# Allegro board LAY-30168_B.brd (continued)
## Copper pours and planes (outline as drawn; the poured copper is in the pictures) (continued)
N99816488 on TOP (solid shape): 101.6,9.68 101.6,6.99 101.6,6.97 101.58,6.95 100.99,5.58 101.58,4.21 101.6,4.19 101.6,4.17 101.6,3.08 101.35,2.83 99.31,2.83 99.06,3.08 99.06,9.68 99.31,9.94 101.35,9.94
N99816488 on BOTTOM (solid shape): 119.25,10.37 119.25,8.54 119,8.29 99.31,8.29 99.06,8.54 99.06,10.54 100.27,11.75 117.87,11.75
N99825452 on TOP (solid shape): 131.6,23.77 132.56,23.77 132.72,23.62 132.72,22.73 132.84,22.61 132.84,21.46 131.83,20.45 131.32,20.45 131.19,20.32 131.19,19.05 130.94,18.8 130.58,18.8 130.56,18.82 130.05,18.82 130.03,18.8 128.02,18.8 127.76,19.05 127.76,19.81 127.76,22.78 127.81,22.83 127.91,22.83 128.02,22.73 128.02,21.67 128.88,20.8 130.3,20.8 131.6,22.1 131.6,23.19 131.42,23.37 130.66,23.37 130.62,23.41 130.57,23.41 130.45,23.52 129.79,23.52 129.72,23.6 129.72,23.7 129.79,23.77 131.6,23.77
N99833003 on TOP (solid shape): 96.27,2.41 96.27,0.76 96.14,0.64 86.61,0.64 86.49,0.76 86.49,2.41 86.74,2.67 96.01,2.67
N99833003 on BOTTOM (solid shape): 96.27,2.41 96.27,0.76 96.14,0.64 86.61,0.64 86.49,0.76 86.49,2.41 86.74,2.67 96.01,2.67
N99833017 on TOP (solid shape): 91.31,7.87 91.31,6.73 91.31,6.7 91.29,6.69 91.16,6.5 91.18,6.27 91.18,6.24 91.16,6.21 91.14,6.18 90.22,6.18 90.14,6.11 90.14,5.26 90.17,5.24 90.17,5.23 90.22,5.14 90.3,5.07 90.32,5.05 90.32,5.03 90.32,3.48 90.3,3.45 90.2,3.45 90.13,3.49 90.1,3.56 90.07,3.78 89.98,3.99 89.97,4 89.97,4.22 89.79,4.4 88.19,4.4 87.88,4.71 87.88,7.34 87.91,7.36 88.82,7.36 89.2,6.98 90.96,6.98 91.03,7.06 91.03,7.87 91.06,7.9 91.29,7.9
N99834989 on TOP (solid shape): 85.6,2.41 85.6,0.76 85.47,0.64 75.95,0.64 75.82,0.76 75.82,2.41 76.07,2.67 85.34,2.67
N99834989 on BOTTOM (solid shape): 85.6,2.41 85.6,0.76 85.47,0.64 75.95,0.64 75.82,0.76 75.82,2.41 76.07,2.67 85.34,2.67
N99834993 on TOP (solid shape): 80.64,7.87 80.64,6.36 80.47,6.18 79.25,6.18 79.15,6.08 79.15,5.69 79.65,5.18 79.65,3.48 79.63,3.45 79.53,3.45 79.46,3.49 79.43,3.56 79.4,3.79 79.3,4 79.3,4.53 79.12,4.71 77.6,4.71 77.22,5.09 77.22,7.34 77.24,7.36 78.16,7.36 78.54,6.98 80.29,6.98 80.37,7.06 80.37,7.87 80.39,7.9 80.62,7.9
N99903738 on TOP (solid shape): 148.34,30.35 148.34,26.8 148.21,26.67 143.38,26.67 143.13,26.92 143.13,27.43 143.38,27.69 145.54,27.69 145.92,28.07 145.92,30.35 146.05,30.48 148.21,30.48
N99912430 on TOP (solid shape): 96.01,65.91 96.01,59.82 95.89,59.69 93.34,59.69 92.84,60.2 92.84,63.23 92.86,63.25 92.86,63.75 92.84,63.77 92.84,64.37 92.86,64.39 92.86,64.9 92.84,64.92 92.84,65.55 92.84,65.56 92.84,65.76 92.84,65.91 92.96,66.04 95.89,66.04
N99912683 on TOP (solid shape): 99.44,65.53 99.44,64.39 99.57,64.26 102.23,64.26 102.36,64.14 102.36,60.21 102.3,60.15 102.3,60.01 102.11,59.82 97.41,59.82 97.16,60.07 97.16,65.91 97.28,66.04 98.93,66.04
N99912703 on TOP (solid shape): 102.23,68.71 102.23,66.55 101.98,66.29 100.2,66.29 99.95,66.55 99.95,68.71 100.2,68.96 101.98,68.96
N99912703 on BOTTOM (solid shape): 101.73,68.96 101.73,65.66 100.71,64.64 94.61,64.64 93.85,65.41 93.85,66.8 93.98,66.93 94.49,66.93 94.61,66.8 94.61,66.17 95.06,65.72 99.63,65.72 100.33,66.42 100.33,68.96 100.46,69.09 101.6,69.09
N100054172 on TOP (solid shape): 24.26,26.04 24.26,21.39 24.24,21.35 24.21,21.34 21.46,21.34 21.34,21.46 21.34,24.77 20.7,25.4 12.7,25.4 11.91,24.61 11.9,24.61 11.85,24.58 11.82,24.52 11.81,24.49 11.81,24.28 11.81,24.27 11.81,20.7 12.06,20.45 12.06,19.53 12.05,19.5 12.01,19.48 10.38,19.48 10.27,19.37 9.51,19.37 9.51,18.9 9.5,18.86 9.46,18.85 7.24,18.85 6.73,19.35 6.73,21.34 6.99,21.59 8.76,21.59 9.14,21.97 9.14,25.4 10.41,26.67 23.62,26.67
N100054299 on TOP (solid shape): 13.34,18.03 13.73,18.03 13.74,18.03 13.94,18.03 14.1,18.03 14.61,18.54 15.24,18.54 15.37,18.41 15.37,16.46 15.16,16.26 13.87,16.26 13.82,16.21 13.82,15.72 13.79,15.7 12.14,15.7 11.83,15.39 9.55,15.39 9.5,15.34 7.29,15.34 6.86,15.77 6.86,18.29 7.11,18.54 8.86,18.54 9.32,18.08 9.75,18.08 9.76,18.08 9.88,18.06 10.01,18.08 10.02,18.08 10.06,18.08 10.29,18.31 10.29,19.02 10.49,19.23 12.14,19.23
N100531599 on TOP (solid shape): 46.74,27.91 47.24,27.91 47.27,27.94 47.88,27.94 48.13,27.69 48.13,26.26 48.13,26.25 48.13,26.05 48.13,26.04 48.13,24.13 47.88,23.88 45.87,23.88 45.72,24.03 45.72,25.65 45.72,26.67 45.72,27.81 45.85,27.94 46.71,27.94
N100538655 on TOP (solid shape): 39.75,37.21 40.77,37.21 40.89,37.08 40.89,36.2 41.02,36.07 42.16,36.07 42.29,35.94 42.29,35.69 42.16,35.56 40.77,35.56 40.77,35.57 40.26,35.57 40.26,35.56 38.48,35.56 38.1,35.94 38.1,37.21 38.23,37.34 39.62,37.34
N101139052 on TOP (solid shape): 85.22,13.97 85.22,12.95 85.52,12.65 86.29,12.65 86.35,12.59 86.35,12.46 86.29,12.4 86.09,12.4 85.96,12.27 85.96,12.07 85.9,12.01 85.11,12.01 84.03,10.92 83.31,10.92 83.2,11.04 83.2,11.05 83.2,11.56 83.19,11.58 83.19,12.21 83.19,12.22 83.19,12.42 83.19,12.43 83.19,12.9 83.2,12.94 83.24,12.95 83.31,12.95 83.31,13.97 83.31,13.97 83.26,14 83.27,14.06 83.44,14.22 84.96,14.22
N101141743 on TOP (solid shape): 88.01,23.75 88.01,22.73 88.31,22.43 89.09,22.43 89.14,22.37 89.14,22.28 88.86,22.28 88.66,22.07 88.66,21.88 87.94,21.88 87.63,21.57 87.63,21.51 87.08,20.95 86.61,20.95 86.61,20.97 86.11,20.97 86,21.08 86,21.34 85.98,21.36 85.98,21.99 85.98,22.21 85.98,22.73 86.11,22.73 86.11,23.75 86.1,23.75 86.06,23.78 86.07,23.84 86.23,24 87.76,24
N101529304 on TOP: 123.32,66.29 126.62,66.29 126.75,66.17 126.75,65.28 126.62,65.15 123.32,65.15 123.19,65.28 123.19,66.17
N101529304 on BOTTOM: 129.92,74.55 131.19,74.55 131.32,74.42 131.32,69.34 126.87,64.9 125.09,64.9 124.97,65.02 124.97,66.29 125.09,66.42 126.36,66.42 129.79,69.85 129.79,74.42

Small or netless copper shapes (teardrops, artwork), in the pictures only: 2 on INT1

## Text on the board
BOTTOM: 170-30168_REV B | 7 | ARTWORK BOTTOM
Ref Des/Silkscreen Bottom: 9 | SILKSCREEN BOTTOM
User.Comments: 3 | 8 | SOLDMASK BOTTOM | SOLDMASK TOP | 1/1 | 1
TOP: 4 | ARTWORK TOP
Ref Des/Silkscreen Top: IS26KS512S | IS25WP064A | DEVICE | SD | BOOT_CFG | 0x02_00 | 0x00_00 | 0x00_40 | 0,0,0,0 | SW5 | SW6 | 0,1,1,0 | 0,0,1,0 | 1,0,1,0 | SW7 | C | A | D | B | 2 | SILKSCREEN TOP | IMXRT1050-EVKB
GND: 5 | ARTWORK LAYER02
INT1: 6 | ARTWORK LAYER03
DIMENSION: A_TARGET:3 MILS | B_TARGET:52 MILS | C_TARGET:3 MILS | If the angle of PCB board outline is circular,please use this kind of break out area | If not use it,please delete it before you gerber out | If the angle of PCB board outline is right angle,please use this kind of break out area | AS usual,please use the 0.8MM stamp Via | SCALE: NONE | .062" THK +/- 10% | LAYER 1  COMPONENT SIDE     1/2oz+plating | LAYER 2  GROUND PLANE       1 oz. | LAYER 3  POWER PLANE        1 oz. | LAYER 4  SOLDER SIDE        1/2oz+plating | FINISHED Cu WEIGHT | 0 | DETAIL A | LAYER STACKUP
BODY_CENTER: V_CUT
FABRICATION_NOTES: 8. | 16. | 1. THIS DRAWING SPECIFIES THE REQUIREMENTS FOR A | 2. THE PWB MUST BE LEAD FREE ASSEMBLY PROCESS COMPATIBLE AND MUST BE ABLE TO HANDLE | 3. BASE MATERIAL - LAMINATE AND PREPREG SHALL MEET IPC-4101B-26, 83 or 98 | Tg - MUST BE GREATER THAN OR EQUAL TO 150 DEGREES CELSIUS. | Td - MUST BE GREATER THAN OR EQUAL TO 330 DEGREES CELSIUS. | 4. COPPER FOIL WEIGHT - SEE STACKUP DETAIL 'A' | 5. CHARACTERISTIC IMPEDANCE - SEE DETAIL 'B' | 6. MINIMUM CONDUCTIVE WIDTH/SPACING TO BE .00X"/.00X" | 7. PLATING FINISH - BOTH SIDES ENIG (ELECTROLESS NICKEL IMMERSION GOLD): | 8. ALL THROUGH HOLE VIAS MAY BE PLATED SHUT. | - MUST BE UL RECOGNIZED AND MUST HAVE AN ID THAT CONFORMS TO UL94V-0 | 9. SOLDERMASK - GREEN COLOR (TAIYO OR EQUIVALENT), BOTH SIDES. | 10. SILKSCREEN - WHITE EPOXY INK, BOTH SIDES.  NO SILK ON PADS. | 11. ELECTRICAL TEST - 100% IPCD356. | 12. PRINTED WIRING BOARD IS TO BE INDIVIDUALLY BAGGED. | 13. DRC'S MUST BE RUN ON THE GERBER BEFORE BUILDING BOARDS, | UNLESS PRIOR APPROVAL IS GIVEN IN WRITING BY FREESCALE. | 14. ADD TEARDROPS TO ALL SIGNAL LAYERS. | 15. SOLDER SAMPLES TO BE PROVIDED. | 16. BASIC GRID INCREMENT AT 1:1 IS .0001. | 17. SUPPLIER MARKINGS - ON SOLDER SIDE ONLY, WHERE SHOWN. | MODIFICATION OF SOLDERMASK IS NOT ALLOWED WITHOUT WRITTEN PERMISSION FROM FREESCALE. | WITH SPECIFICATION IPC-A-600 CLASS 2 (LATEST REVISION). | A MINIMUM OF 5 CYCLES AT 260 DEGREES CELSIUS FOR 10 SECONDS. | 18. THE PWB WILL BE MARKED AS LEAD FREE BY USE OF AN INK STAMP Pb | 19. THE PWB WILL BE MARKED AS LEAD FREE PROCESS COMPATIBLE BY USE OF AN INK STAMP 260 C | 21. FINISHED PCB MUST BE PANELIZED FOR ASSEMBLY ACCORDING TO CONTRACT MANUFACTURING REQUIREMENT. | ADDITION OF .25" RAILS AND .125" NON-PLATED TOOLING HOLES ARE AT THE DISCRETION | OF CONTRACT MANUFACTURER AND FAB HOUSE. | PANELIZATION MUST BE APPROVED BY FREESCALE. | 2.540-6.350 MICRON (100-250 MICROINCH) OF NICKEL. | .05080-.232 MICRON (2-8 MICROINCH) OF GOLD OVER | PRINTED WIRING BOARD IN ACCORDANCE | 20. ALL PLATED AND NON-PLATED THROUGH HOLES ARE TO BE DRILLED AT PRIMARY DRILL STEP. | ALL HOLE LOCATION TOLERANCES ARE TO BE +/-.002 IN REFERENCE TO THE PRIMARY DATUM. | DETAIL B | IMPEDANCE REQUIREMENTS | IMPEDANCE TOLERANCE IS 10%
User.5: 10 | PASTEMASK_BOTTOM
User.6: 1 | PASTEMASK_TOP
User.11: 6501 WILLIAM CANNON DRIVE WEST | AUSTIN. TEXAS 78735 USA | SHEET | THIS DOCUMENT CONTAINS INFORMATION | PROPRIETARY TO FREESCALE AND SHALL | NOT BE USED FOR ENGINEERING DESIGN | PROCUREMENT OR MANUFACTURE IN WHOLE | OR IN PART WITHOUT THE CONSENT OF | NXP. | OF 10 | FILM | NAME | DATE | 11-07-18 | ___ PUBI (PUBLIC INFORMATION) | ___ FIUO (NXP INTERNAL USE ONLY) | ___ FCP (NXP CONFIDENTIAL PROPRIETARY) | NUMBER | X | 170-30168     REV B | IMXRT1050_EVKB | NXP SEMICONDUCTOR
User.17: FIGURE | SIZE | 8.0 | 26.0 | 28.0 | 30.0 | 36.0 | 40.0 | 41.0 | 45.0 | 63.0 | 139.0 | 22.0 | 59.0 | 118.0 | 59.0x20.0 | 79.0x40.0 | 86.61x47.24 | 118.0x31.0 | 137.8x31.5 | DRILL CHART: TOP to BOTTOM | ALL UNITS ARE IN MILS | TOLERANCE | +3.0/-3.0 | +2.0/-2.0 | PLATED | NON-PLATED | QTY | 1674 | 10 | 6 | 2 | 26 | 58 | 20 | 4 | 1
User.18: Trace Width | (Mils) | Impedance | (Ohms) | Trace Spacing | "Airgap" | L1 | L4 | 5.00 | 50 | 4.2 | 6.00 | 100 | 4.70 | 90 | Layers | Single Ended | Differential
User.19: ___ PUBI (PUBLIC INFORMATION) | ___ FIUO (NXP INTERNAL USE ONLY) | ___ FCP (NXP CONFIDENTIAL PROPRIETARY) | THIS DOCUMENT CONTAINS INFORMATION | PROPRIETARY TO FREESCALE AND SHALL | NOT BE USED FOR ENGINEERING DESIGN | PROCUREMENT OR MANUFACTURE IN WHOLE | OR IN PART WITHOUT THE CONSENT OF | NXP. | 6501 WILLIAM CANNON DRIVE WEST  AUSTIN, TEXAS 78735 USA | X | Shawn Shi | Albert Li | 11-07-18 | 12-21-17 | SHAWN | A | B | REPLACE OPENSDA CHIP WITH LPC | LAY-30168 | 170-30168 | PRINTED WIRING BOARD | IMXRT1050-EVKB | FAB-30168 | NXP SEMICONDUCTOR
